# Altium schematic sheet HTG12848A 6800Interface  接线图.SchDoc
size A4
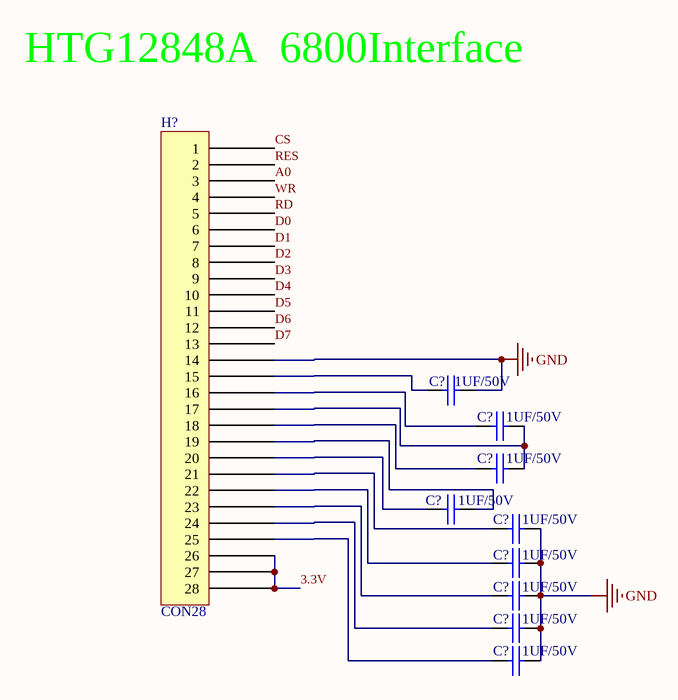
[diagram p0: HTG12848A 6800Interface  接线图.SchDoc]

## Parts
(Parts that share a designator on the sheet are numbered #1, #2 ... from top to bottom, then left to right.)
C?#1  1UF/50V  [0805CAP]
C?#2  1UF/50V  [0805CAP]
C?#3  1UF/50V  [0805CAP]
C?#4  1UF/50V  [0805CAP]
C?#5  1UF/50V  [0805CAP]
C?#6  1UF/50V  [0805CAP]
C?#7  1UF/50V  [0805CAP]
C?#8  1UF/50V  [0805CAP]
C?#9  1UF/50V  [0805CAP]
H?  CON28

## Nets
GND: C?#1.2 C?#5.2 C?#6.2 C?#7.2 C?#8.2 C?#9.2 H?.14
3.3V: H?.26 H?.27 H?.28
A0: H?.3
CS: H?.1
D0: H?.6
D1: H?.7
D2: H?.8
D3: H?.9
D4: H?.10
D5: H?.11
D6: H?.12
D7: H?.13
RD: H?.5
RES: H?.2
WR: H?.4
NetC?#1_1: C?#1.1 H?.15
NetC?#2_1: C?#2.1 H?.16
NetC?#2_2: C?#2.2 C?#3.2 H?.17
NetC?#3_1: C?#3.1 H?.18
NetC?#4_1: C?#4.1 H?.19
NetC?#4_2: C?#4.2 H?.20
NetC?#5_1: C?#5.1 H?.21
NetC?#6_1: C?#6.1 H?.22
NetC?#7_1: C?#7.1 H?.23
NetC?#8_1: C?#8.1 H?.24
NetC?#9_1: C?#9.1 H?.25

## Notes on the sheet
- HTG12848A  6800Interface

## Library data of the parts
C?#1-C?#9 = CAP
